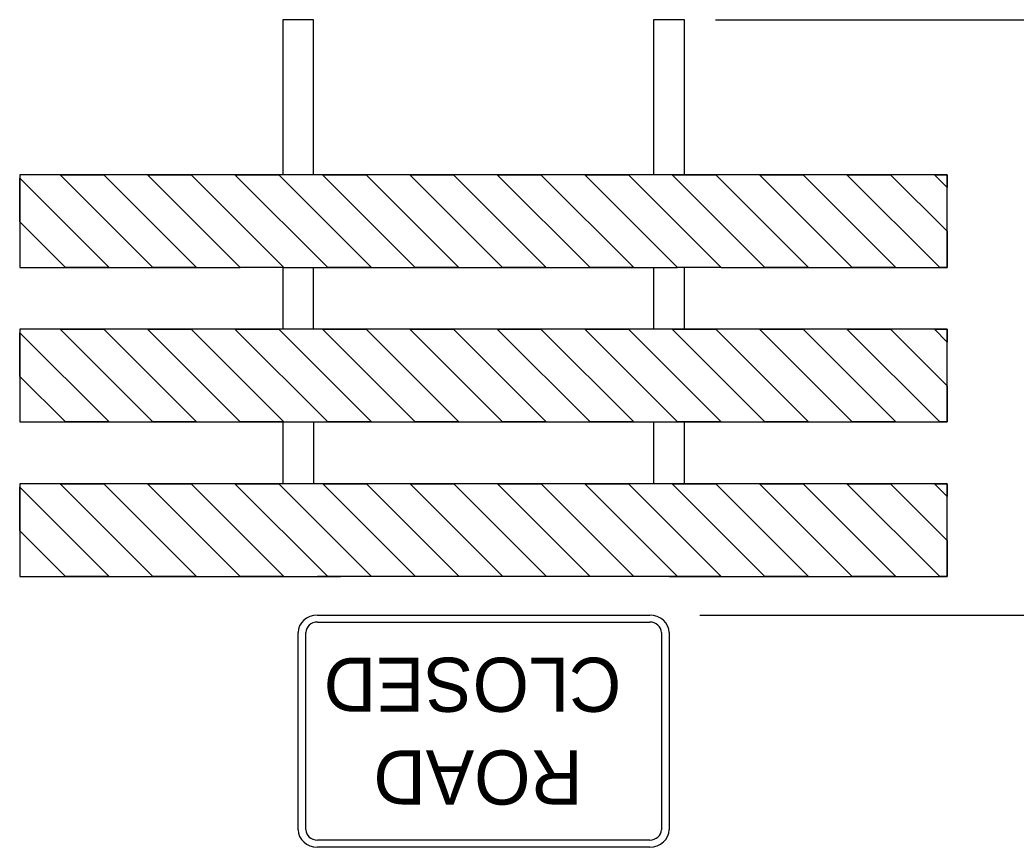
# Model space of a CAD drawing. Extents: x 49991.4 to 50021, y 49987.6 to 50011.4.
# Drawn here: x 50011.644 to 50012.933, y 49990.664 to 49991.734 of the extents above; entities that cross this region are included whole.
import ezdxf

# ---------------------------------------------------------------- set-up
doc = ezdxf.new("R2010")
doc.units = 0
doc.layers.add('Level 1', color=7, linetype='Continuous')
doc.layers.add('Level 3', color=7, linetype='Continuous')

msp = doc.modelspace()

# ---------------------------------------------------------------- linework, layer by layer
at = {"layer": 'Level 1'}
for p, q in [((50011.644, 49991.529), (50011.7595, 49991.4134)), ((50011.644, 49991.529), (50011.7595, 49991.4134)), ((50011.6961, 49991.5334), (50011.8161, 49991.4134)), ((50011.8161, 49991.4134), (50011.6961, 49991.5334)), ((50011.7526, 49991.5334), (50011.8726, 49991.4134)), ((50011.7526, 49991.5334), (50011.8726, 49991.4134)), ((50011.8092, 49991.5334), (50011.9292, 49991.4134)), ((50011.9292, 49991.4134), (50011.8092, 49991.5334)), ((50011.8657, 49991.5334), (50011.9857, 49991.4134)), ((50011.8657, 49991.5334), (50011.9857, 49991.4134)), ((50011.9223, 49991.5334), (50012.0423, 49991.4134)), ((50012.0423, 49991.4134), (50011.9223, 49991.5334)), ((50011.9789, 49991.5334), (50012.0989, 49991.4134)), ((50011.9789, 49991.5334), (50012.0989, 49991.4134)), ((50012.0354, 49991.5334), (50012.1554, 49991.4134)), ((50012.1554, 49991.4134), (50012.0354, 49991.5334)), ((50012.092, 49991.5334), (50012.212, 49991.4134)), ((50012.092, 49991.5334), (50012.212, 49991.4134)), ((50012.1485, 49991.5334), (50012.2685, 49991.4134)), ((50012.2685, 49991.4134), (50012.1485, 49991.5334)), ((50012.2051, 49991.5334), (50012.3251, 49991.4134)), ((50012.2051, 49991.5334), (50012.3251, 49991.4134)), ((50012.2617, 49991.5334), (50012.3817, 49991.4134)), ((50012.3817, 49991.4134), (50012.2617, 49991.5334)), ((50012.3182, 49991.5334), (50012.4382, 49991.4134)), ((50012.3182, 49991.5334), (50012.4382, 49991.4134)), ((50012.3748, 49991.5334), (50012.4948, 49991.4134)), ((50012.4948, 49991.4134), (50012.3748, 49991.5334)), ((50012.4313, 49991.5334), (50012.5513, 49991.4134)), ((50012.4313, 49991.5334), (50012.5513, 49991.4134)), ((50012.4879, 49991.5334), (50012.6079, 49991.4134)), ((50012.6079, 49991.4134), (50012.4879, 49991.5334)), ((50012.5445, 49991.5334), (50012.6645, 49991.4134)), ((50012.5445, 49991.5334), (50012.6645, 49991.4134)), ((50012.601, 49991.5334), (50012.721, 49991.4134)), ((50012.721, 49991.4134), (50012.601, 49991.5334)), ((50012.6576, 49991.5334), (50012.7776, 49991.4134)), ((50012.6576, 49991.5334), (50012.7776, 49991.4134)), ((50012.7142, 49991.5334), (50012.8342, 49991.4134)), ((50012.8342, 49991.4134), (50012.7142, 49991.5334)), ((50012.7707, 49991.5334), (50012.844, 49991.4602)), ((50012.7707, 49991.5334), (50012.844, 49991.4602)), ((50012.8273, 49991.5334), (50012.844, 49991.5167)), ((50012.844, 49991.5167), (50012.8273, 49991.5334)), ((50011.644, 49991.4724), (50011.7029, 49991.4134)), ((50011.7029, 49991.4134), (50011.644, 49991.4724)), ((50011.6961, 49991.3335), (50011.8161, 49991.2135)), ((50011.8161, 49991.2135), (50011.6961, 49991.3335)), ((50011.7526, 49991.3335), (50011.8726, 49991.2135)), ((50011.7526, 49991.3335), (50011.8726, 49991.2135)), ((50011.8092, 49991.3335), (50011.9292, 49991.2135)), ((50011.9292, 49991.2135), (50011.8092, 49991.3335)), ((50011.8657, 49991.3335), (50011.9857, 49991.2135)), ((50011.8657, 49991.3335), (50011.9857, 49991.2135)), ((50011.9223, 49991.3335), (50012.0423, 49991.2135)), ((50011.9789, 49991.3335), (50012.0989, 49991.2135)), ((50012.0354, 49991.3335), (50012.1554, 49991.2135)), ((50012.092, 49991.3335), (50012.212, 49991.2135)), ((50012.1485, 49991.3335), (50012.2685, 49991.2135)), ((50012.2051, 49991.3335), (50012.3251, 49991.2135)), ((50012.2617, 49991.3335), (50012.3817, 49991.2135)), ((50012.3182, 49991.3335), (50012.4382, 49991.2135)), ((50012.3748, 49991.3335), (50012.484, 49991.2243)), ((50012.4313, 49991.3335), (50012.484, 49991.2808)), ((50012.4879, 49991.3335), (50012.6079, 49991.2135)), ((50012.6079, 49991.2135), (50012.4879, 49991.3335)), ((50012.5445, 49991.3335), (50012.6645, 49991.2135)), ((50012.5445, 49991.3335), (50012.6645, 49991.2135)), ((50012.601, 49991.3335), (50012.721, 49991.2135)), ((50012.721, 49991.2135), (50012.601, 49991.3335)), ((50012.6576, 49991.3335), (50012.7776, 49991.2135)), ((50012.6576, 49991.3335), (50012.7776, 49991.2135)), ((50012.7142, 49991.3335), (50012.8342, 49991.2135)), ((50012.8342, 49991.2135), (50012.7142, 49991.3335)), ((50012.7707, 49991.3335), (50012.844, 49991.2603)), ((50012.7707, 49991.3335), (50012.844, 49991.2603)), ((50012.8273, 49991.3335), (50012.844, 49991.3168)), ((50012.844, 49991.3168), (50012.8273, 49991.3335)), ((50011.644, 49991.329), (50011.7595, 49991.2135)), ((50011.644, 49991.329), (50011.7595, 49991.2135)), ((50011.644, 49991.2725), (50011.7029, 49991.2135)), ((50011.7029, 49991.2135), (50011.644, 49991.2725)), ((50012.484, 49991.2808), (50012.5513, 49991.2135)), ((50012.484, 49991.2243), (50012.4948, 49991.2135)), ((50012.024, 49991.2135), (50012.024, 49991.1336)), ((50012.464, 49991.2135), (50012.464, 49991.1336)), ((50011.644, 49991.1291), (50011.7595, 49991.0136)), ((50011.644, 49991.1291), (50011.7595, 49991.0136)), ((50011.6961, 49991.1336), (50011.8161, 49991.0136)), ((50011.8161, 49991.0136), (50011.6961, 49991.1336)), ((50011.7526, 49991.1336), (50011.8726, 49991.0136)), ((50011.7526, 49991.1336), (50011.8726, 49991.0136)), ((50011.8092, 49991.1336), (50011.9292, 49991.0136)), ((50011.9292, 49991.0136), (50011.8092, 49991.1336)), ((50011.8657, 49991.1336), (50011.9857, 49991.0136)), ((50011.8657, 49991.1336), (50011.9857, 49991.0136)), ((50011.9223, 49991.1336), (50012.0423, 49991.0136)), ((50011.9789, 49991.1336), (50012.0989, 49991.0136)), ((50012.0358, 49991.1336), (50012.1558, 49991.0136)), ((50012.0923, 49991.1336), (50012.2123, 49991.0136)), ((50012.1488, 49991.1336), (50012.2688, 49991.0136)), ((50012.2053, 49991.1336), (50012.3253, 49991.0136)), ((50012.2618, 49991.1336), (50012.3818, 49991.0136)), ((50012.3183, 49991.1336), (50012.4383, 49991.0136)), ((50012.3748, 49991.1336), (50012.4948, 49991.0136)), ((50012.4313, 49991.1336), (50012.5513, 49991.0136)), ((50012.4879, 49991.1336), (50012.6079, 49991.0136)), ((50012.6079, 49991.0136), (50012.4879, 49991.1336)), ((50012.5445, 49991.1336), (50012.6645, 49991.0136)), ((50012.5445, 49991.1336), (50012.6645, 49991.0136)), ((50012.601, 49991.1336), (50012.721, 49991.0136)), ((50012.721, 49991.0136), (50012.601, 49991.1336)), ((50012.6576, 49991.1336), (50012.7776, 49991.0136)), ((50012.6576, 49991.1336), (50012.7776, 49991.0136)), ((50012.7142, 49991.1336), (50012.8342, 49991.0136)), ((50012.8342, 49991.0136), (50012.7142, 49991.1336)), ((50012.7707, 49991.1336), (50012.844, 49991.0603)), ((50012.7707, 49991.1336), (50012.844, 49991.0603)), ((50012.8273, 49991.1336), (50012.844, 49991.1169)), ((50012.844, 49991.1169), (50012.8273, 49991.1336)), ((50011.644, 49991.0725), (50011.7029, 49991.0136)), ((50011.7029, 49991.0136), (50011.644, 49991.0725)), ((50012.004, 49991.0136), (50012.059, 49991.0136)), ((50012.459, 49991.0136), (50012.029, 49991.0136)), ((50012.4948, 49991.0136), (50012.4248, 49991.0136)), ((50012.029, 49990.9636), (50012.459, 49990.9636)), ((50012.029, 49990.9546), (50012.459, 49990.9546)), ((50012.004, 49990.6861), (50012.004, 49990.9411)), ((50012.014, 49990.6861), (50012.014, 49990.9411)), ((50012.474, 49990.9411), (50012.474, 49990.6861)), ((50012.484, 49990.9411), (50012.484, 49990.6861)), ((50012.459, 49990.6726), (50012.029, 49990.6726)), ((50012.459, 49990.6636), (50012.029, 49990.6636))]:
    msp.add_line(p, q, dxfattribs=at)
for points in [[(50012.024, 49991.5336), (50012.024, 49991.7336), (50011.984, 49991.7336), (50011.984, 49991.5336)], [(50012.504, 49991.5336), (50012.504, 49991.7336), (50012.464, 49991.7336), (50012.464, 49991.5336)], [(50012.5513, 49991.4134), (50012.844, 49991.4134), (50012.844, 49991.5334), (50011.644, 49991.5334), (50011.644, 49991.4134), (50011.9292, 49991.4134)], [(50011.644, 49991.4724), (50011.644, 49991.529)], [(50011.6961, 49991.5334), (50011.7526, 49991.5334)], [(50011.8092, 49991.5334), (50011.8657, 49991.5334)], [(50011.9223, 49991.5334), (50011.9789, 49991.5334)], [(50012.0354, 49991.5334), (50012.092, 49991.5334)], [(50012.1485, 49991.5334), (50012.2051, 49991.5334)], [(50012.2617, 49991.5334), (50012.3182, 49991.5334)], [(50012.3748, 49991.5334), (50012.4313, 49991.5334)], [(50012.4879, 49991.5334), (50012.5445, 49991.5334)], [(50012.601, 49991.5334), (50012.6576, 49991.5334)], [(50012.7142, 49991.5334), (50012.7707, 49991.5334)], [(50012.8273, 49991.5334), (50012.844, 49991.5334), (50012.844, 49991.5167)], [(50012.844, 49991.4602), (50012.844, 49991.4134), (50012.8342, 49991.4134)], [(50011.7595, 49991.4134), (50011.7029, 49991.4134)], [(50011.8726, 49991.4134), (50011.8161, 49991.4134)], [(50011.9857, 49991.4134), (50011.9292, 49991.4134)], [(50011.984, 49991.4134), (50011.984, 49991.3335)], [(50011.9857, 49991.4134), (50012.4948, 49991.4134)], [(50012.024, 49991.3335), (50012.024, 49991.4134)], [(50012.0989, 49991.4134), (50012.0423, 49991.4134)], [(50012.212, 49991.4134), (50012.1554, 49991.4134)], [(50012.3251, 49991.4134), (50012.2685, 49991.4134)], [(50012.4382, 49991.4134), (50012.3817, 49991.4134)], [(50012.464, 49991.4134), (50012.464, 49991.3335)], [(50012.5513, 49991.4134), (50012.4948, 49991.4134)], [(50012.504, 49991.3335), (50012.504, 49991.4134)], [(50012.6645, 49991.4134), (50012.6079, 49991.4134)], [(50012.7776, 49991.4134), (50012.721, 49991.4134)], [(50012.484, 49991.2135), (50012.844, 49991.2135), (50012.844, 49991.3335), (50011.644, 49991.3335), (50011.644, 49991.2135), (50012.484, 49991.2135)], [(50011.6961, 49991.3335), (50011.7526, 49991.3335)], [(50011.8092, 49991.3335), (50011.8657, 49991.3335)], [(50012.0989, 49991.2135), (50012.0423, 49991.2135), (50011.9223, 49991.3335), (50011.9789, 49991.3335), (50012.0989, 49991.2135)], [(50012.212, 49991.2135), (50012.1554, 49991.2135), (50012.0354, 49991.3335), (50012.092, 49991.3335), (50012.212, 49991.2135)], [(50012.3251, 49991.2135), (50012.2685, 49991.2135), (50012.1485, 49991.3335), (50012.2051, 49991.3335), (50012.3251, 49991.2135)], [(50012.4382, 49991.2135), (50012.3817, 49991.2135), (50012.2617, 49991.3335), (50012.3182, 49991.3335), (50012.4382, 49991.2135)], [(50012.3748, 49991.3335), (50012.4313, 49991.3335), (50012.484, 49991.2808), (50012.5513, 49991.2135), (50012.504, 49991.2135), (50012.4948, 49991.2135), (50012.484, 49991.2243), (50012.3748, 49991.3335)], [(50012.4879, 49991.3335), (50012.5445, 49991.3335)], [(50012.601, 49991.3335), (50012.6576, 49991.3335)], [(50012.7142, 49991.3335), (50012.7707, 49991.3335)], [(50012.8273, 49991.3335), (50012.844, 49991.3335), (50012.844, 49991.3168)], [(50011.644, 49991.2725), (50011.644, 49991.329)], [(50012.844, 49991.2603), (50012.844, 49991.2135), (50012.8342, 49991.2135)], [(50011.7595, 49991.2135), (50011.7029, 49991.2135)], [(50011.8726, 49991.2135), (50011.8161, 49991.2135)], [(50011.9857, 49991.2135), (50011.9292, 49991.2135)], [(50011.984, 49991.2136), (50011.984, 49991.1336)], [(50012.504, 49991.1336), (50012.504, 49991.2135)], [(50012.6645, 49991.2135), (50012.6079, 49991.2135)], [(50012.7776, 49991.2135), (50012.721, 49991.2135)], [(50012.484, 49991.1336), (50011.644, 49991.1336), (50011.644, 49991.0136), (50012.004, 49991.0136)], [(50011.644, 49991.0725), (50011.644, 49991.1291)], [(50011.6961, 49991.1336), (50011.7526, 49991.1336)], [(50011.8092, 49991.1336), (50011.8657, 49991.1336)], [(50012.0989, 49991.0136), (50012.059, 49991.0136), (50012.0423, 49991.0136), (50011.9223, 49991.1336), (50011.9789, 49991.1336), (50012.0989, 49991.0136)], [(50012.2123, 49991.0136), (50012.1558, 49991.0136), (50012.0358, 49991.1336), (50012.0923, 49991.1336), (50012.2123, 49991.0136)], [(50012.3253, 49991.0136), (50012.2688, 49991.0136), (50012.1488, 49991.1336), (50012.2053, 49991.1336), (50012.3253, 49991.0136)], [(50012.4383, 49991.0136), (50012.4248, 49991.0136), (50012.3818, 49991.0136), (50012.2618, 49991.1336), (50012.3183, 49991.1336), (50012.4383, 49991.0136)], [(50012.3748, 49991.1336), (50012.4313, 49991.1336), (50012.5513, 49991.0136), (50012.4948, 49991.0136), (50012.3748, 49991.1336)], [(50012.484, 49991.0136), (50012.844, 49991.0136), (50012.844, 49991.1336), (50012.484, 49991.1336)], [(50012.4879, 49991.1336), (50012.5445, 49991.1336)], [(50012.601, 49991.1336), (50012.6576, 49991.1336)], [(50012.7142, 49991.1336), (50012.7707, 49991.1336)], [(50012.8273, 49991.1336), (50012.844, 49991.1336), (50012.844, 49991.1169)], [(50012.844, 49991.0603), (50012.844, 49991.0136), (50012.8342, 49991.0136)], [(50011.7595, 49991.0136), (50011.7029, 49991.0136)], [(50011.8726, 49991.0136), (50011.8161, 49991.0136)], [(50011.9857, 49991.0136), (50011.9292, 49991.0136)], [(50012.6645, 49991.0136), (50012.6079, 49991.0136)], [(50012.7776, 49991.0136), (50012.721, 49991.0136)]]:
    msp.add_lwpolyline(points, dxfattribs=at)
for centre, major_axis, start_param, end_param in [((50012.029, 49990.9411), (-0.025, 0), 4.712389, 6.283185), ((50012.459, 49990.9411), (-0.025, 0), 3.141593, 4.712389), ((50012.029, 49990.9411), (-0.015, 0), 4.712389, 6.283185), ((50012.459, 49990.9411), (-0.015, 0), 3.141593, 4.712389), ((50012.029, 49990.6861), (0.025, 0), 3.141593, 4.712389), ((50012.029, 49990.6861), (0.015, 0), 3.141593, 4.712389), ((50012.459, 49990.6861), (0.025, 0), 4.712389, 6.283185), ((50012.459, 49990.6861), (0.015, 0), 4.712389, 6.283185)]:
    msp.add_ellipse(centre, major_axis=major_axis, ratio=0.9, start_param=start_param, end_param=end_param, dxfattribs=at)
at = {"layer": 'Level 3'}
for p, q in [((50012.544, 49991.7336), (50013.6769, 49991.7336)), ((50012.459, 49990.9636), (50012.459, 49990.9636)), ((50012.524, 49990.9636), (50013.6769, 49990.9636))]:
    msp.add_line(p, q, dxfattribs=at)

# ---------------------------------------------------------------- texts
at = {"layer": 'Level 1'}
for s, p in [('CLOSED', (50012.4223, 49990.9086)), ('ROAD', (50012.3721, 49990.7886))]:
    msp.add_text(s, height=0.07, rotation=180, dxfattribs=at).set_placement(p)

doc.saveas('drawing.dxf')
